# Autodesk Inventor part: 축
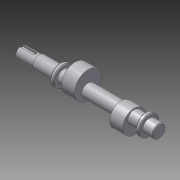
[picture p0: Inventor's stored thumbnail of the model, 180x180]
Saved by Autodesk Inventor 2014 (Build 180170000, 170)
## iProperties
Created: 2014-12
Part Number: 축
Material: 알루미늄 6061
Document SubType Name: Modeling
Designer: Owner
Density: 2.71 g/cm^3
Appearance: 알루미늄 - 평지
Mass: 170.354 g
Surface Area: 153.402 cm^2
Volume: 62.8614 cm^3
Author: Owner
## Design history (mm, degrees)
sketch "스케치1"
  geometry: L1 (-90, 0)-(90, 0); L2 (-90, 0)-(-90, 7.5); L3 (-90, 7.5)-(-66, 7.5); L4 (-66, 7.5)-(-66, 8.5); L5 (-66, 8.5)-(-39, 8.5); L6 (-39, 8.5)-(-39, 13); L7 (-39, 13)-(-34, 13); L8 (-34, 13)-(-34, 8.5); L9 (-34, 8.5)-(72, 8.5); L10 (72, 8.5)-(72, 13); L11 (72, 13)-(77, 13); L12 (77, 13)-(77, 8.5); L13 (77, 8.5)-(90, 8.5); L14 (90, 8.5)-(90, 0); 7 further points
  constraints: 28 end point, 6 midpoint, 6 parallel, 4 perpendicular, 3 collinear, 3 horizontal alignment, 2 horizontal, 1 coincident
  dimensions: "d0" = 180 distance of L1.start L1.end; "d1" = 15 diameter of L3 L1; "d2" = 24 distance between parallel lines of L4 L2; "d3" = 32 distance between parallel lines of L4 L8; "d4" = 5 distance of L6.end L7.end; "d5" = 26 diameter of L7 L1; "d6" = 17 diameter of L5 L1; "d7" = 13 distance between parallel lines of L14 L12
revolve "회전1" sketch "스케치1" stored, may be unused: angle "d8" = 90 deg
node "작업 평면1"
sketch "스케치2"
  geometry: C1 r 17.5 at (-6, 0); 1 further point
  constraints: 1 centre point, 1 horizontal alignment
  dimensions: "d10" = 35 diameter of C1; "d11" = 6 distance of point (0, 0) C1.centre
extrude "돌출1" join sketch "스케치2" distance "d12" = 17; taper "d13" = 0 deg
node "작업 평면2"
sketch "스케치3"
  geometry: C1 r 15 at (-5, 0); 1 further point
  constraints: 1 centre point, 1 horizontal alignment
  dimensions: "d15" = 30 diameter of C1; "d16" = 5 distance of C1.centre point (0, 0)
extrude "돌출2" join sketch "스케치3" distance "d17" = 17; taper "d18" = 0 deg
node "작업 평면3"
sketch "스케치4"
  geometry: L1 (-12, -7.5)-(-12, 7.5) reference; L2 (-12, 2.5)-(5.5, 2.5); L3 (-12, -2.5)-(5.5, -2.5); A1 r 2.5 centre (5.5, 0) between (5.5, -2.5) and (5.5, 2.5); 3 further points
  constraints: 4 end point, 3 point on circle, 2 point on line, 2 tangent, 1 centre point, 1 horizontal alignment, 1 midpoint, 1 parallel, 1 perpendicular
  dimensions: "d19" = 5 diameter of A1; "d20" = 20 dimension on A1 L1
extrude "돌출3" cut sketch "스케치4" distance "d21" = 3; taper "d22" = 0 deg
chamfer "모따기1" distance "d23" = 1; stored, may be unused: second distance "d24" = 2, angle "d25" = 45 deg
node "솔리드1"
other parameters: "d9" = 14.5, "d14" = 14.5
